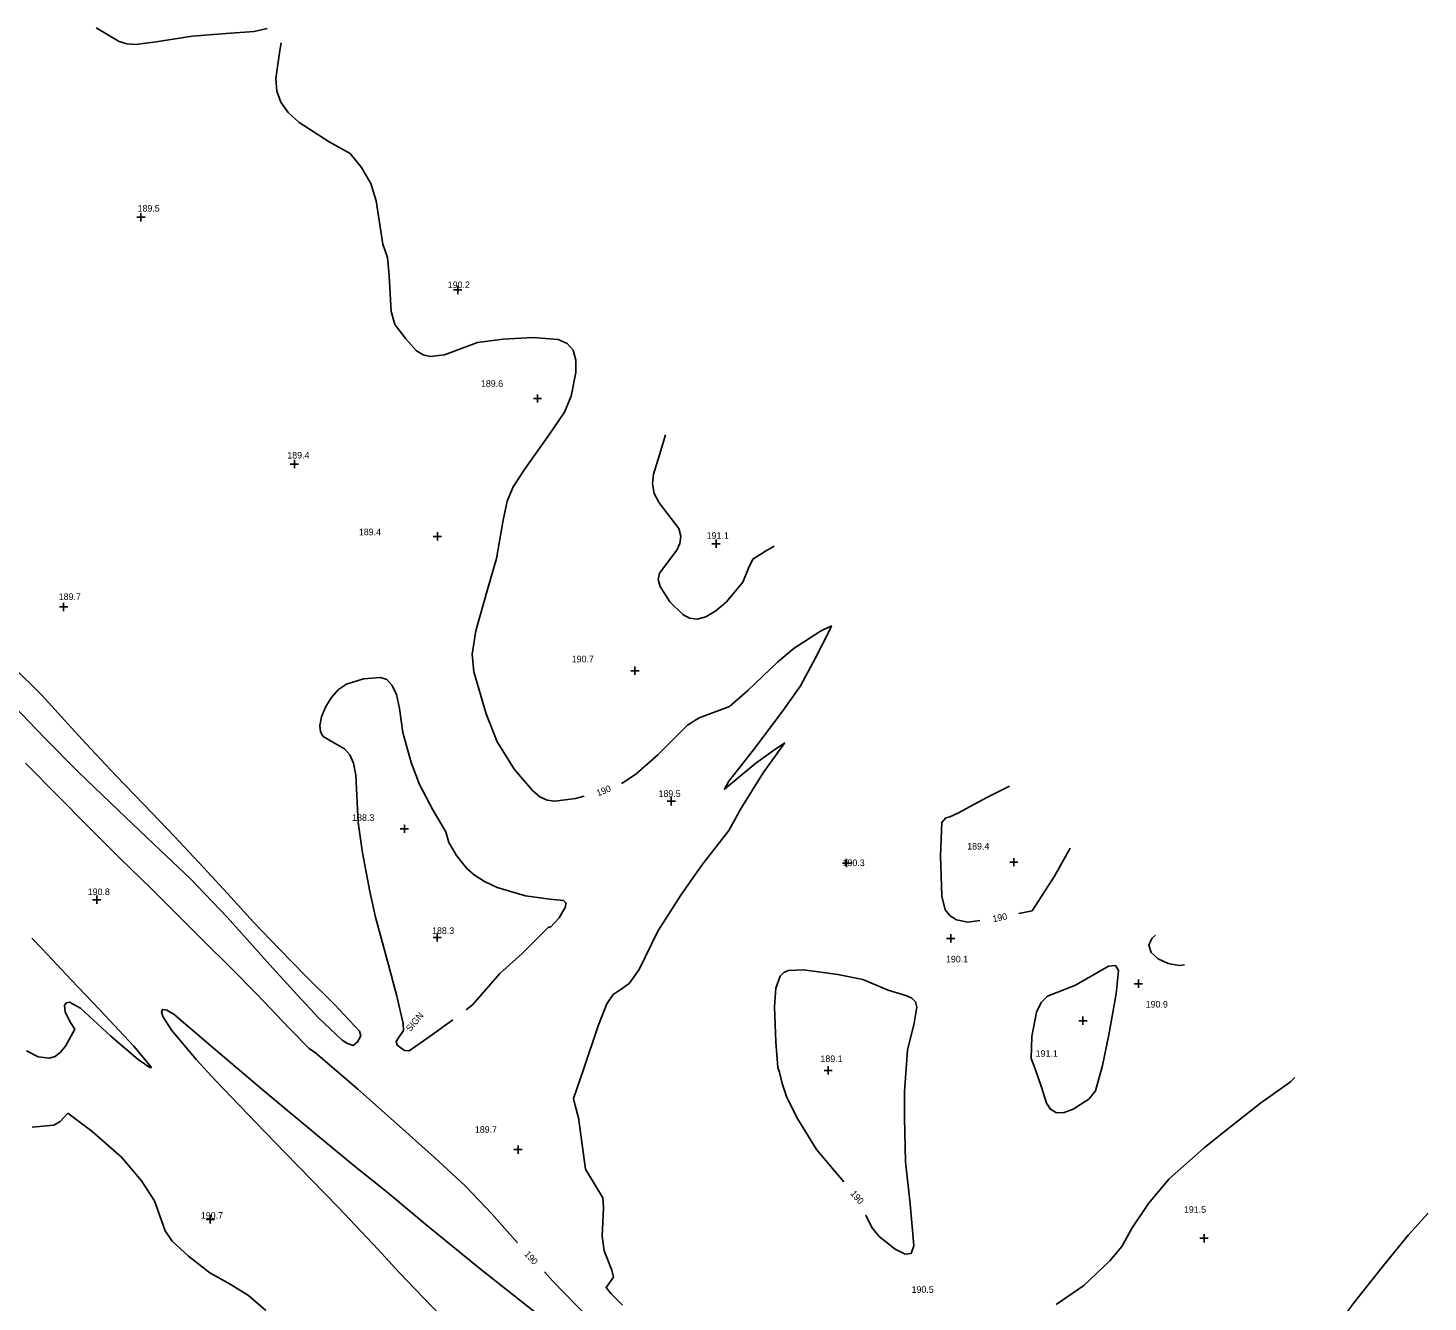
# Model space of a CAD drawing. Extents: x 1467615 to 2003689, y 770235 to 1108726.
# Drawn here: x 1992871 to 1993295.1, y 778980.4 to 779366.2 of the extents above; entities that cross this region are included whole.
import ezdxf

# ---------------------------------------------------------------- set-up
doc = ezdxf.new("R2010")
doc.units = 0
for name, color, linetype in [('RD_DTM_Major1', 7, 'Continuous'), ('RD_DTM_Major1_Lbl', 7, 'Continuous'), ('RD_DTM_Minor1', 7, 'Continuous'), ('RD_DTM_Spot_Elev', 7, 'Continuous'), ('RD_TX_Misc1', 7, 'Continuous')]:
    doc.layers.add(name, color=color, linetype=linetype)

msp = doc.modelspace()

# ---------------------------------------------------------------- linework, layer by layer
at = {"layer": 'RD_DTM_Major1'}
for points in [[(1992891.64, 779366.24), (1992898.63, 779362.15), (1992900.97, 779361.41), (1992903.63, 779361.22), (1992909.86, 779362.03), (1992920.78, 779363.77), (1992932.39, 779364.68), (1992939.53, 779365.18), (1992943.46, 779366.11)], [(1992947.76, 779361.72), (1992947.36, 779359.47), (1992946.12, 779350.93), (1992946.44, 779347.12), (1992947.65, 779343.73), (1992949.85, 779340.61), (1992953.12, 779337.59), (1992962.26, 779331.72), (1992968.57, 779328.18), (1992972.05, 779324), (1992974.84, 779319.13), (1992976.49, 779313.87), (1992978.54, 779300.77), (1992979.93, 779296.74), (1992980.39, 779291.16), (1992981.02, 779280.38), (1992982.17, 779276.46), (1992985.46, 779272.05), (1992988.73, 779268.47), (1992990.68, 779267.24), (1992992.81, 779266.72), (1992997.16, 779267.3), (1993007.18, 779271), (1993014.98, 779272.04), (1993023.97, 779272.49), (1993031.59, 779271.89), (1993034.36, 779270.72), (1993036.19, 779268.66), (1993037, 779265.61), (1993036.97, 779261.93), (1993035.51, 779254.7), (1993033.52, 779249.86), (1993029.01, 779243.21), (1993021.38, 779232.51), (1993017.95, 779227.29), (1993016.18, 779222.91), (1993014.99, 779217.19), (1993012.93, 779205.53), (1993010.21, 779196.15), (1993006.64, 779183.67), (1993005.54, 779176.62), (1993006.07, 779171.21), (1993009.8, 779158.51), (1993013.16, 779150), (1993018.35, 779141.63), (1993023.82, 779135.28), (1993026.11, 779133.42), (1993028.27, 779132.42), (1993030.59, 779132.1), (1993036.83, 779132.9), (1993039.45, 779133.58)], [(1993050.83, 779137.47), (1993050.98, 779137.53), (1993055.16, 779140.25), (1993061.79, 779146.07), (1993070.77, 779155.14), (1993074.35, 779157.36), (1993083.49, 779160.71), (1993089.04, 779165.58), (1993098.07, 779174.16), (1993103.08, 779178.46), (1993111.03, 779183.53), (1993114.38, 779185.13), (1993113.84, 779183.8), (1993109.49, 779175.25), (1993105.04, 779167.04), (1993099.64, 779159.47), (1993090.82, 779147.59), (1993083.33, 779138.16), (1993081.98, 779135.7), (1993091.48, 779143.57), (1993097.26, 779147.69), (1993100.18, 779149.65), (1993093.67, 779140.7), (1993087.06, 779129.99), (1993083.27, 779123.23), (1993075.12, 779112.66), (1993068.82, 779103.6), (1993061.77, 779092.68), (1993056.11, 779081.11), (1993053.14, 779076.86), (1993050.39, 779074.89), (1993048.23, 779073.54), (1993046.32, 779070.69), (1993043.74, 779064.02), (1993039.25, 779050.84), (1993036.31, 779042.05), (1993036.74, 779039.93), (1993037.77, 779036.14), (1993038.92, 779028.06), (1993039.93, 779020.65), (1993045.1, 779011.96), (1993045.34, 779008.87), (1993044.92, 779000.38), (1993045.59, 778995.88), (1993047.83, 778990.01), (1993048.4, 778987.87), (1993046.11, 778984.82), (1993047.72, 778982.91), (1993051.14, 778979.39)], [(1993019.3, 778998.33), (1993011.5, 779007.15), (1993003.48, 779015.55), (1992994.19, 779024.19), (1992982.7, 779034.43), (1992970.9, 779044.89), (1992958.07, 779055.9), (1992956.19, 779057.2), (1992950.27, 779063.28), (1992940.32, 779073.59), (1992932.63, 779081.36), (1992923.97, 779090.03), (1992908.3, 779105.58), (1992899.1, 779114.65), (1992888.78, 779124.95), (1992880.25, 779133.53), (1992870.26, 779143.62)], [(1993159.31, 779095.94), (1993155.75, 779095.46), (1993152.3, 779096.09), (1993150.32, 779097.4), (1993148.84, 779099.15), (1993147.84, 779103.31), (1993147.39, 779115.51), (1993147.81, 779125.57), (1993149.02, 779127.04), (1993150.2, 779127.3), (1993152.65, 779128.4), (1993161.42, 779133.21), (1993168.33, 779136.62)], [(1993186.74, 779117.83), (1993181.99, 779109.39), (1993175.15, 779098.87), (1993171.13, 779098.03)], [(1992872.24, 779090.56), (1992875.46, 779087.28), (1992884.14, 779077.95), (1992892.68, 779068.96), (1992903.14, 779057.89), (1992908.4, 779051.46), (1992907.9, 779051.43), (1992904.44, 779053.84), (1992896.13, 779060.86), (1992886.98, 779069.41), (1992883.61, 779071.25), (1992882.65, 779071.02), (1992882.13, 779070.29), (1992882.26, 779068.14), (1992883.95, 779065.09), (1992885.21, 779063.02), (1992882.35, 779057.85), (1992880.93, 779056.07), (1992879.3, 779054.77), (1992877.52, 779054.23), (1992874.16, 779054.68), (1992870.55, 779056.42)], [(1993118.19, 779016.78), (1993115.31, 779020.11), (1993109.91, 779026.57), (1993104.22, 779035.74), (1993100.84, 779042.37), (1993099.45, 779046.56), (1993098.63, 779050.04), (1993098.18, 779051.45), (1993097.53, 779059.1), (1993097.12, 779069.8), (1993097.57, 779075.47), (1993098.88, 779079.12), (1993099.92, 779080.19), (1993101.35, 779080.81), (1993105.89, 779080.96), (1993116.34, 779079.6), (1993123.86, 779078.08), (1993131.62, 779074.87), (1993137.24, 779073.16), (1993138.73, 779072.38), (1993139.8, 779071.27), (1993140.28, 779069.68), (1993139.49, 779064.89), (1993137.46, 779056.63), (1993136.56, 779044.15), (1993136.53, 779036.2), (1993136.87, 779022.84), (1993138.25, 779010.1), (1993139.3, 778997.36), (1993138.52, 778995.06), (1993136.69, 778994.91), (1993133.67, 778996.42), (1993128.8, 779000.28), (1993126.6, 779002.93), (1993124.82, 779006.65)], [(1993040.85, 778975.64), (1993029.99, 778986.73), (1993027.43, 778989.5)]]:
    msp.add_lwpolyline(points, dxfattribs=at)
at = {"layer": 'RD_DTM_Minor1'}
msp.add_line((1992999.71, 779065.88), (1992992.8, 779060.95), dxfattribs=at)
for points in [[(1993064.08, 779243.02), (1993062.46, 779237.3), (1993060.53, 779231.14), (1993060.19, 779228.16), (1993060.69, 779225.25), (1993062.22, 779222.43), (1993068.12, 779214.65), (1993068.76, 779212.32), (1993068.51, 779210.12), (1993067.61, 779208.09), (1993062.28, 779201.11), (1993061.93, 779199.2), (1993062.47, 779197.05), (1993065.47, 779192.48), (1993069.37, 779188.65), (1993071.42, 779187.49), (1993073.7, 779187.15), (1993076.35, 779187.86), (1993079.42, 779189.74), (1993082.59, 779192.44), (1993087.59, 779198.37), (1993089.31, 779202.64), (1993090.55, 779205.42), (1993094.46, 779207.8), (1993097.08, 779209.33)], [(1992866.27, 779173.05), (1992875.31, 779164.07), (1992882.09, 779156.64), (1992888.59, 779149.5), (1992897.65, 779139.87), (1992906.16, 779131.06), (1992915.53, 779121.28), (1992924.17, 779112.01), (1992931.51, 779104.08), (1992939.37, 779095.45), (1992947.17, 779087.3), (1992955.11, 779079.18), (1992963.85, 779070.52), (1992971.49, 779062.44), (1992971.83, 779061.05), (1992970.84, 779059.18), (1992969.51, 779058.11), (1992967.8, 779058.66), (1992966.24, 779059.69), (1992959.01, 779066.51), (1992952.65, 779073.29), (1992945.2, 779081.47), (1992931.32, 779096.9), (1992920.16, 779108.7), (1992911.11, 779117.27), (1992898.3, 779129.36), (1992886.31, 779140.91), (1992876.04, 779151.26), (1992864.57, 779163.31)], [(1992992.8, 779060.95), (1992986.52, 779056.46), (1992985.1, 779056.52), (1992982.88, 779058.22), (1992982.54, 779059.28), (1992983.46, 779060.72), (1992984.76, 779062.58), (1992984.72, 779064.77), (1992982.71, 779073), (1992980.18, 779082.56), (1992976.33, 779096.9), (1992974.62, 779104.76), (1992972.34, 779116.48), (1992971.07, 779125.65), (1992970.33, 779139.92), (1992969.67, 779143.55), (1992968.5, 779146.15), (1992966.94, 779147.89), (1992963.37, 779149.91), (1992960.42, 779151.71), (1992959.59, 779153.07), (1992959.39, 779155), (1992959.92, 779157.58), (1992961.12, 779160.53), (1992962.88, 779163.42), (1992965.06, 779165.85), (1992967.55, 779167.53), (1992972.62, 779169.09), (1992977.78, 779169.55), (1992979.71, 779168.91), (1992981.38, 779167.06), (1992982.69, 779164.42), (1992983.59, 779160.16), (1992984.56, 779152.89), (1992987.08, 779143.77), (1992989.62, 779137.14), (1992993.61, 779129.45), (1992997.55, 779122.75), (1992998.54, 779119.61), (1993000.84, 779115.58), (1993003.92, 779111.71), (1993006.27, 779109.66), (1993009.33, 779107.71), (1993013.15, 779105.98), (1993021.75, 779103.45), (1993029.05, 779102.43), (1993033.22, 779102), (1993033.97, 779101.31), (1993033.82, 779100.03), (1993031.93, 779096.71), (1993029.25, 779093.94), (1993028.67, 779093.93), (1993026.53, 779091.78), (1993020.68, 779085.96), (1993013.92, 779079.89), (1993005.82, 779070.49), (1993003.76, 779068.91)], [(1993212.56, 779091.48), (1993211.39, 779090.52), (1993210.52, 779088.44), (1993211.28, 779086.27), (1993213.39, 779084.31), (1993216.36, 779082.87), (1993219.71, 779082.28), (1993221.35, 779082.51)], [(1993177.87, 779071.15), (1993176.49, 779068.18), (1993175.06, 779060.81), (1993174.89, 779054.11), (1993176.1, 779051.03), (1993178.02, 779045.44), (1993179.56, 779040.64), (1993180.77, 779038.75), (1993182.51, 779037.73), (1993184.88, 779037.84), (1993187.57, 779038.82), (1993192.3, 779041.83), (1993194.35, 779044.32), (1993196.5, 779052.04), (1993198.36, 779061.3), (1993200.66, 779073.75), (1993201.31, 779080.77), (1993200.4, 779082.34), (1993198.32, 779082.07), (1993188.35, 779076.37), (1993179.79, 779073.02), (1993177.87, 779071.15)], [(1993024.34, 778977.53), (1993007.95, 778990.47), (1992992.18, 779003.36), (1992980.4, 779013.18), (1992969.26, 779022.14), (1992958.7, 779030.83), (1992942.44, 779044.32), (1992927.86, 779056.81), (1992915.27, 779067.52), (1992913.12, 779068.78), (1992911.85, 779069), (1992911.44, 779068.32), (1992911.86, 779066.89), (1992914.64, 779062.58), (1992922.05, 779053.77), (1992927.88, 779047.43), (1992940.14, 779034.69), (1992948.87, 779025.68), (1992964.94, 779009.1), (1992977.05, 778996.32), (1992983.57, 778989.24), (1992995.94, 778976.3)], [(1993254.78, 779048.4), (1993253.44, 779047.12), (1993244.31, 779040.58), (1993232.94, 779031.66), (1993227.26, 779027.06), (1993216.69, 779017.74), (1993210.47, 779010.28), (1993205.5, 779002.82), (1993202.39, 778997.22), (1993198.66, 778992.87), (1993190.82, 778985.39), (1993182.48, 778979.64)], [(1992943.04, 778977.85), (1992937.79, 778982.35), (1992932.3, 778985.83), (1992926.1, 778989.26), (1992919.67, 778994.25), (1992914.66, 778998.87), (1992912.59, 779001.93), (1992909.31, 779011.01), (1992905.38, 779017.13), (1992899.38, 779024.23), (1992890.35, 779032.18), (1992883.08, 779037.56), (1992880.8, 779035.08), (1992878.91, 779033.92), (1992872.31, 779033.32)], [(1993295.08, 779007.27), (1993289.19, 779000.76), (1993281.64, 778991.45), (1993272.68, 778980.2), (1993268.77, 778975.03), (1993266.89, 778967.06), (1993262.03, 778956.34), (1993255.22, 778942.29), (1993254.14, 778939.12), (1993254.57, 778937.24), (1993256.24, 778934.57), (1993258.68, 778931.32), (1993258.49, 778928.65), (1993259.44, 778928.58), (1993261.67, 778928.33), (1993261.61, 778927.48), (1993260.34, 778925.33)]]:
    msp.add_lwpolyline(points, dxfattribs=at)
at = {"layer": 'RD_DTM_Spot_Elev'}
for p, q in [((1992904, 779308.92), (1992906.5, 779308.92)), ((1992905.25, 779307.67), (1992905.25, 779310.17)), ((1992999.94, 779286.92), (1993002.44, 779286.92)), ((1993001.19, 779285.67), (1993001.19, 779288.17)), ((1993024.11, 779254.02), (1993026.61, 779254.02)), ((1993025.36, 779252.77), (1993025.36, 779255.27)), ((1992951.72, 779232.91), (1992951.72, 779235.41)), ((1992950.47, 779234.16), (1992952.97, 779234.16)), ((1992995.05, 779211.02), (1992995.05, 779213.52)), ((1992993.8, 779212.27), (1992996.3, 779212.27)), ((1993078.19, 779210.06), (1993080.69, 779210.06)), ((1993079.44, 779208.81), (1993079.44, 779211.31)), ((1992880.57, 779190.9), (1992883.07, 779190.9)), ((1992881.82, 779189.65), (1992881.82, 779192.15)), ((1993053.63, 779171.6), (1993056.13, 779171.6)), ((1993054.88, 779170.35), (1993054.88, 779172.85)), ((1993065.87, 779130.81), (1993065.87, 779133.31)), ((1993064.62, 779132.06), (1993067.12, 779132.06)), ((1992985.05, 779122.46), (1992985.05, 779124.96)), ((1992983.8, 779123.71), (1992986.3, 779123.71)), ((1993117.73, 779113.32), (1993120.23, 779113.32)), ((1993118.98, 779112.07), (1993118.98, 779114.57)), ((1993168.39, 779113.61), (1993170.89, 779113.61)), ((1993169.64, 779112.36), (1993169.64, 779114.86)), ((1992891.84, 779100.98), (1992891.84, 779103.48)), ((1992890.59, 779102.23), (1992893.09, 779102.23)), ((1992993.71, 779090.79), (1992996.21, 779090.79)), ((1992994.96, 779089.54), (1992994.96, 779092.04)), ((1993149.27, 779090.53), (1993151.77, 779090.53)), ((1993150.52, 779089.28), (1993150.52, 779091.78)), ((1993207.37, 779075.54), (1993207.37, 779078.04)), ((1993206.12, 779076.79), (1993208.62, 779076.79)), ((1993189.33, 779065.6), (1993191.83, 779065.6)), ((1993190.58, 779064.35), (1993190.58, 779066.85)), ((1993112.14, 779050.54), (1993114.64, 779050.54)), ((1993113.39, 779049.29), (1993113.39, 779051.79)), ((1993019.48, 779025.29), (1993019.48, 779027.79)), ((1993018.23, 779026.54), (1993020.73, 779026.54)), ((1992926.26, 779004.16), (1992926.26, 779006.66)), ((1992925.01, 779005.41), (1992927.51, 779005.41)), ((1993226.01, 778999.71), (1993228.51, 778999.71)), ((1993227.26, 778998.46), (1993227.26, 779000.96))]:
    msp.add_line(p, q, dxfattribs=at)

# ---------------------------------------------------------------- texts
at = {"layer": 'RD_DTM_Major1_Lbl'}
for rotation, p in [(22.1815, (1993043.7, 779133.48)), (11.7012, (1993163.4, 779095.41)), (310.8031, (1993119.98, 779013.18)), (312.7535, (1993021.2, 778994.77))]:
    msp.add_text('190', height=2, rotation=rotation, dxfattribs=at).set_placement(p)
at = {"layer": 'RD_DTM_Spot_Elev'}
for s, p in [('190.9', (1993209.59, 779069.57)), ('191.1', (1993176.25, 779054.65)), ('189.7', (1993006.38, 779031.65)), ('191.5', (1993221.16, 779007.41)), ('190.5', (1993138.67, 778983.17))]:
    msp.add_text(s, height=2, dxfattribs=at).set_placement(p)
at = {"layer": 'RD_TX_Misc1'}
for s, p in [('189.5', (1992904.24, 779310.62)), ('190.2', (1992998.18, 779287.46)), ('189.6', (1993008.23, 779257.57)), ('189.4', (1992949.58, 779235.85)), ('189.4', (1992971.26, 779212.61)), ('191.1', (1993076.6, 779211.53)), ('189.7', (1992880.35, 779193)), ('190.7', (1993035.71, 779174.12)), ('189.5', (1993062.02, 779133.35)), ('188.3', (1992969.22, 779126.11)), ('189.4', (1993155.51, 779117.43)), ('190.3', (1993117.76, 779112.41)), ('190.8', (1992889.13, 779103.63)), ('188.3', (1992993.42, 779091.87)), ('190.1', (1993149.09, 779083.24)), ('189.1', (1993111.06, 779053.06)), ('190.7', (1992923.4, 779005.61))]:
    msp.add_text(s, height=2, dxfattribs=at).set_placement(p)
msp.add_text('SIGN', height=2, rotation=50.3392, dxfattribs=at).set_placement((1992986.83, 779062.1))

doc.saveas('drawing.dxf')
